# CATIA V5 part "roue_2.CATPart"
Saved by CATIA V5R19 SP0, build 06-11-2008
Part number: skl_roue_2
Publications: "axe_pivot_roue2_batit", "lineaire_rect_roue2_sabot2", "Plan.1", "contour_roue2"
Bounding box of the stored display mesh (mm): x -766.832 to -233.168, y 3.332 to 536.668, z -20 to 20
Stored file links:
  C:\Users\Thibaud\Desktop\IFMA\thinkmotion\IAO\modele_catia\squelette\roue_2.CATPart
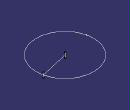
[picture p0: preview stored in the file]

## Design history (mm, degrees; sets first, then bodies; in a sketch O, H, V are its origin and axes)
Body1 (main body)
  Point1: stored without definition
  Point2: stored without definition
  Line1: type PtPt, SecondPoint Point2, FirstPoint Point1
  Point3: stored without definition
  Plane1: stored without definition
  Line2 "lineaire_rect_roue2_sabot2": type Normal, RefSkin Plane1, Start -20, End 20, RefPoint Point3
  Plane2: stored without definition
  Point4: stored without definition
  Line3 "axe_pivot_roue2_batit": type Normal, RefSkin Plane2, Start -20, End 20, RefPoint Point4
  Point5: stored without definition
  Point6: stored without definition
  Plane3: stored without definition
  Circle1 "contour_roue2": type CtrPt, Start 0, End 180, Support Plane3, Center Point5, RefPoint Point6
